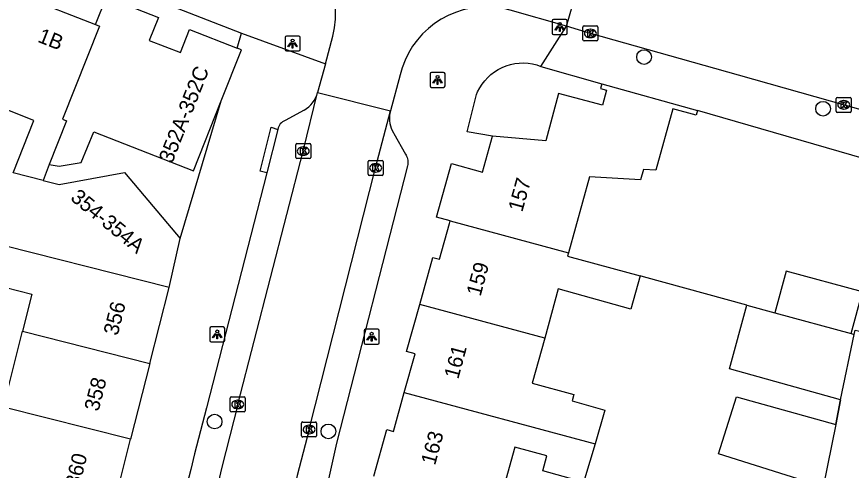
# Model space of a CAD drawing. Extents: x 161253 to 161848, y 384872 to 385383.
# Drawn here: x 161649.5 to 161705.2, y 385069.1 to 385099.3 of the extents above; entities that cross this region are included whole.
import ezdxf

# ---------------------------------------------------------------- set-up
doc = ezdxf.new("R2010")
doc.units = 0
for name, color, linetype in [('IMGEO_Boom', 7, 'Continuous'), ('IMGEO_Erf', 7, 'Continuous'), ('IMGEO_Hek', 7, 'Continuous'), ('IMGEO_Kolk', 7, 'Continuous'), ('IMGEO_Lichtpunt', 7, 'Continuous'), ('IMGEO_Pand', 7, 'Continuous'), ('IMGEO_Pand_nummerreeks', 7, 'Continuous'), ('IMGEO_Rijbaan_lokaal_open', 7, 'Continuous'), ('IMGEO_Voetpad_open', 7, 'Continuous')]:
    doc.layers.add(name, color=color, linetype=linetype)

msp = doc.modelspace()

# ---------------------------------------------------------------- linework, layer by layer
at = {"layer": 'IMGEO_Boom'}
for centre in [(161691.332, 385096.626), (161703.264, 385093.176), (161662.69, 385072.315), (161670.276, 385071.655)]:
    msp.add_circle(centre, 0.489, dxfattribs=at)
at = {"layer": 'IMGEO_Erf'}
msp.add_lwpolyline([(161698.188, 385080.085), (161691.283, 385081.97), (161691.078, 385082.026)], dxfattribs=at)
at = {"layer": 'IMGEO_Hek'}
msp.add_lwpolyline([(161704.441, 385073.771), (161704.117, 385072.125)], dxfattribs=at)
at = {"layer": 'IMGEO_Kolk'}
for p, q in [((161687.251, 385097.773), (161687.251, 385098.625)), ((161687.326, 385098.699), (161688.178, 385098.699)), ((161687.739, 385098.479), (161687.764, 385098.479)), ((161688.252, 385098.625), (161688.252, 385097.773)), ((161688.178, 385097.699), (161687.326, 385097.699)), ((161687.762, 385097.919), (161687.737, 385097.919)), ((161704.15, 385093.01), (161704.15, 385093.862)), ((161704.225, 385093.936), (161705.077, 385093.936)), ((161705.151, 385093.862), (161705.151, 385093.01)), ((161704.638, 385093.716), (161704.663, 385093.716)), ((161705.077, 385092.936), (161704.225, 385092.936)), ((161704.661, 385093.156), (161704.636, 385093.156)), ((161668.101, 385089.924), (161668.101, 385090.776)), ((161668.176, 385090.85), (161669.028, 385090.85)), ((161668.589, 385090.63), (161668.614, 385090.63)), ((161669.102, 385090.776), (161669.102, 385089.924)), ((161669.028, 385089.85), (161668.176, 385089.85)), ((161668.612, 385090.07), (161668.587, 385090.07)), ((161672.931, 385088.806), (161672.931, 385089.658)), ((161673.006, 385089.732), (161673.858, 385089.732)), ((161673.419, 385089.512), (161673.444, 385089.512)), ((161673.932, 385089.658), (161673.932, 385088.806)), ((161673.858, 385088.732), (161673.006, 385088.732)), ((161673.442, 385088.952), (161673.417, 385088.952)), ((161663.736, 385073.03), (161663.736, 385073.882)), ((161663.811, 385073.956), (161664.663, 385073.956)), ((161664.224, 385073.736), (161664.249, 385073.736)), ((161664.737, 385073.882), (161664.737, 385073.03)), ((161664.247, 385073.176), (161664.222, 385073.176)), ((161664.663, 385072.956), (161663.811, 385072.956)), ((161668.496, 385071.357), (161668.496, 385072.209)), ((161668.571, 385072.283), (161669.423, 385072.283)), ((161668.984, 385072.063), (161669.009, 385072.063)), ((161669.497, 385072.209), (161669.497, 385071.357)), ((161669.007, 385071.503), (161668.982, 385071.503)), ((161669.423, 385071.283), (161668.571, 385071.283))]:
    msp.add_line(p, q, dxfattribs=at)
for points in [[(161687.251, 385097.773), (161687.251, 385098.625)], [(161687.326, 385098.699), (161688.178, 385098.699)], [(161687.572, 385098.399), (161687.695, 385098.399), (161687.695, 385098.248), (161687.825, 385098.399), (161687.989, 385098.399), (161687.843, 385098.248), (161687.996, 385097.999), (161687.844, 385097.999), (161687.759, 385098.163), (161687.695, 385098.096), (161687.695, 385097.999), (161687.572, 385097.999), (161687.572, 385098.399)], [(161688.252, 385098.625), (161688.252, 385097.773)], [(161688.178, 385097.699), (161687.326, 385097.699)], [(161704.15, 385093.01), (161704.15, 385093.862)], [(161704.225, 385093.936), (161705.077, 385093.936)], [(161705.151, 385093.862), (161705.151, 385093.01)], [(161704.471, 385093.636), (161704.594, 385093.636), (161704.594, 385093.485), (161704.724, 385093.636), (161704.888, 385093.636), (161704.742, 385093.485), (161704.895, 385093.236), (161704.743, 385093.236), (161704.658, 385093.4), (161704.594, 385093.333), (161704.594, 385093.236), (161704.471, 385093.236), (161704.471, 385093.636)], [(161705.077, 385092.936), (161704.225, 385092.936)], [(161668.101, 385089.924), (161668.101, 385090.776)], [(161668.176, 385090.85), (161669.028, 385090.85)], [(161668.422, 385090.55), (161668.545, 385090.55), (161668.545, 385090.399), (161668.675, 385090.55), (161668.839, 385090.55), (161668.693, 385090.399), (161668.846, 385090.15), (161668.694, 385090.15), (161668.609, 385090.314), (161668.545, 385090.247), (161668.545, 385090.15), (161668.422, 385090.15), (161668.422, 385090.55)], [(161669.102, 385090.776), (161669.102, 385089.924)], [(161669.028, 385089.85), (161668.176, 385089.85)], [(161672.931, 385088.806), (161672.931, 385089.658)], [(161673.006, 385089.732), (161673.858, 385089.732)], [(161673.252, 385089.432), (161673.375, 385089.432), (161673.375, 385089.281), (161673.505, 385089.432), (161673.669, 385089.432), (161673.523, 385089.281), (161673.676, 385089.032), (161673.524, 385089.032), (161673.439, 385089.196), (161673.375, 385089.129), (161673.375, 385089.032), (161673.252, 385089.032), (161673.252, 385089.432)], [(161673.932, 385089.658), (161673.932, 385088.806)], [(161673.858, 385088.732), (161673.006, 385088.732)], [(161663.736, 385073.03), (161663.736, 385073.882)], [(161663.811, 385073.956), (161664.663, 385073.956)], [(161664.737, 385073.882), (161664.737, 385073.03)], [(161664.057, 385073.656), (161664.18, 385073.656), (161664.18, 385073.505), (161664.31, 385073.656), (161664.474, 385073.656), (161664.328, 385073.505), (161664.481, 385073.256), (161664.329, 385073.256), (161664.244, 385073.42), (161664.18, 385073.353), (161664.18, 385073.256), (161664.057, 385073.256), (161664.057, 385073.656)], [(161664.663, 385072.956), (161663.811, 385072.956)], [(161668.496, 385071.357), (161668.496, 385072.209)], [(161668.571, 385072.283), (161669.423, 385072.283)], [(161669.497, 385072.209), (161669.497, 385071.357)], [(161668.817, 385071.983), (161668.94, 385071.983), (161668.94, 385071.832), (161669.07, 385071.983), (161669.234, 385071.983), (161669.088, 385071.832), (161669.241, 385071.583), (161669.089, 385071.583), (161669.004, 385071.747), (161668.94, 385071.68), (161668.94, 385071.583), (161668.817, 385071.583), (161668.817, 385071.983)], [(161669.423, 385071.283), (161668.571, 385071.283)]]:
    msp.add_lwpolyline(points, dxfattribs=at)
for centre, start, end in [((161687.328, 385098.623), 91.552, 178.448), ((161687.328, 385098.623), 91.552, 178.448), ((161688.176, 385098.623), 1.552, 88.448), ((161688.176, 385098.623), 1.552, 88.448), ((161687.328, 385097.775), 181.552, 268.448), ((161687.328, 385097.775), 181.552, 268.448), ((161688.176, 385097.775), 271.552, 358.448), ((161688.176, 385097.775), 271.552, 358.448), ((161704.227, 385093.86), 91.552, 178.448), ((161704.227, 385093.86), 91.552, 178.448), ((161705.075, 385093.86), 1.552, 88.448), ((161705.075, 385093.86), 1.552, 88.448), ((161704.227, 385093.012), 181.552, 268.448), ((161704.227, 385093.012), 181.552, 268.448), ((161705.075, 385093.012), 271.552, 358.448), ((161705.075, 385093.012), 271.552, 358.448), ((161668.178, 385090.774), 91.552, 178.448), ((161668.178, 385090.774), 91.552, 178.448), ((161669.026, 385090.774), 1.552, 88.448), ((161669.026, 385090.774), 1.552, 88.448), ((161668.178, 385089.926), 181.552, 268.448), ((161668.178, 385089.926), 181.552, 268.448), ((161669.026, 385089.926), 271.552, 358.448), ((161669.026, 385089.926), 271.552, 358.448), ((161673.008, 385089.656), 91.552, 178.448), ((161673.008, 385089.656), 91.552, 178.448), ((161673.856, 385089.656), 1.552, 88.448), ((161673.856, 385089.656), 1.552, 88.448), ((161673.008, 385088.808), 181.552, 268.448), ((161673.008, 385088.808), 181.552, 268.448), ((161673.856, 385088.808), 271.552, 358.448), ((161673.856, 385088.808), 271.552, 358.448), ((161663.813, 385073.88), 91.552, 178.448), ((161663.813, 385073.88), 91.552, 178.448), ((161664.661, 385073.88), 1.552, 88.448), ((161664.661, 385073.88), 1.552, 88.448), ((161663.813, 385073.032), 181.552, 268.448), ((161663.813, 385073.032), 181.552, 268.448), ((161664.661, 385073.032), 271.552, 358.448), ((161664.661, 385073.032), 271.552, 358.448), ((161668.573, 385072.207), 91.552, 178.448), ((161668.573, 385072.207), 91.552, 178.448), ((161669.421, 385072.207), 1.552, 88.448), ((161669.421, 385072.207), 1.552, 88.448), ((161668.573, 385071.359), 181.552, 268.448), ((161668.573, 385071.359), 181.552, 268.448), ((161669.421, 385071.359), 271.552, 358.448), ((161669.421, 385071.359), 271.552, 358.448)]:
    msp.add_arc(centre, 0.0765, start, end, dxfattribs=at)
for centre, major_axis, ratio, start_param, end_param in [((161687.738, 385098.199), (-0.387, 0.002), 0.722429, 4.712389, 7.853982), ((161687.763, 385098.199), (-0.39, 0.002), 0.717154, 1.570796, 4.712389), ((161704.637, 385093.436), (-0.387, 0.002), 0.722429, 4.712389, 7.853982), ((161704.662, 385093.436), (-0.39, 0.002), 0.717154, 1.570796, 4.712389), ((161668.588, 385090.35), (-0.387, 0.002), 0.722429, 4.712389, 7.853982), ((161668.613, 385090.35), (-0.39, 0.002), 0.717154, 1.570796, 4.712389), ((161673.418, 385089.232), (-0.387, 0.002), 0.722429, 4.712389, 7.853982), ((161673.443, 385089.232), (-0.39, 0.002), 0.717154, 1.570796, 4.712389), ((161664.223, 385073.456), (-0.387, 0.002), 0.722429, 4.712389, 7.853982), ((161664.248, 385073.456), (-0.39, 0.002), 0.717154, 1.570796, 4.712389), ((161668.983, 385071.783), (-0.387, 0.002), 0.722429, 4.712389, 7.853982), ((161669.008, 385071.783), (-0.39, 0.002), 0.717154, 1.570796, 4.712389)]:
    msp.add_ellipse(centre, major_axis=major_axis, ratio=ratio, start_param=start_param, end_param=end_param, dxfattribs=at)
at = {"layer": 'IMGEO_Lichtpunt'}
for p, q in [((161685.206, 385099.031), (161685.206, 385098.224)), ((161685.206, 385099.031), (161685.206, 385098.224)), ((161686.108, 385099.126), (161685.3, 385099.126)), ((161686.108, 385099.126), (161685.3, 385099.126)), ((161686.202, 385098.224), (161686.202, 385099.031)), ((161686.202, 385098.224), (161686.202, 385099.031)), ((161667.396, 385097.93), (161667.396, 385097.123)), ((161667.396, 385097.93), (161667.396, 385097.123)), ((161668.298, 385098.025), (161667.49, 385098.025)), ((161668.298, 385098.025), (161667.49, 385098.025)), ((161668.392, 385097.123), (161668.392, 385097.93)), ((161668.392, 385097.123), (161668.392, 385097.93)), ((161685.3, 385098.13), (161686.108, 385098.13)), ((161685.3, 385098.13), (161686.108, 385098.13)), ((161667.49, 385097.029), (161668.298, 385097.029)), ((161667.49, 385097.029), (161668.298, 385097.029)), ((161677.061, 385095.502), (161677.061, 385094.695)), ((161677.061, 385095.502), (161677.061, 385094.695)), ((161677.963, 385095.597), (161677.155, 385095.597)), ((161677.963, 385095.597), (161677.155, 385095.597)), ((161678.057, 385094.695), (161678.057, 385095.502)), ((161678.057, 385094.695), (161678.057, 385095.502)), ((161677.155, 385094.601), (161677.963, 385094.601)), ((161677.155, 385094.601), (161677.963, 385094.601)), ((161662.368, 385078.528), (161662.368, 385077.721)), ((161662.368, 385078.528), (161662.368, 385077.721)), ((161663.27, 385078.623), (161662.462, 385078.623)), ((161663.27, 385078.623), (161662.462, 385078.623)), ((161663.364, 385077.721), (161663.364, 385078.528)), ((161663.364, 385077.721), (161663.364, 385078.528)), ((161672.666, 385078.371), (161672.666, 385077.564)), ((161672.666, 385078.371), (161672.666, 385077.564)), ((161673.568, 385078.466), (161672.76, 385078.466)), ((161673.568, 385078.466), (161672.76, 385078.466)), ((161673.662, 385077.564), (161673.662, 385078.371)), ((161673.662, 385077.564), (161673.662, 385078.371)), ((161662.462, 385077.627), (161663.27, 385077.627)), ((161662.462, 385077.627), (161663.27, 385077.627)), ((161672.76, 385077.47), (161673.568, 385077.47)), ((161672.76, 385077.47), (161673.568, 385077.47))]:
    msp.add_line(p, q, dxfattribs=at)
for points in [[(161685.58, 385098.695), (161685.619, 385098.667), (161685.431, 385098.405), (161685.393, 385098.432), (161685.58, 385098.695)], [(161685.682, 385098.647), (161685.729, 385098.647), (161685.729, 385098.325), (161685.682, 385098.325), (161685.682, 385098.647)], [(161685.792, 385098.667), (161685.83, 385098.694), (161686.017, 385098.432), (161685.978, 385098.404), (161685.792, 385098.667)], [(161667.77, 385097.594), (161667.809, 385097.566), (161667.621, 385097.304), (161667.583, 385097.331), (161667.77, 385097.594)], [(161667.872, 385097.546), (161667.919, 385097.546), (161667.919, 385097.224), (161667.872, 385097.224), (161667.872, 385097.546)], [(161667.982, 385097.566), (161668.02, 385097.593), (161668.207, 385097.331), (161668.168, 385097.303), (161667.982, 385097.566)], [(161677.435, 385095.166), (161677.474, 385095.138), (161677.286, 385094.876), (161677.248, 385094.903), (161677.435, 385095.166)], [(161677.537, 385095.118), (161677.584, 385095.118), (161677.584, 385094.796), (161677.537, 385094.796), (161677.537, 385095.118)], [(161677.647, 385095.138), (161677.685, 385095.165), (161677.872, 385094.903), (161677.833, 385094.875), (161677.647, 385095.138)], [(161662.742, 385078.192), (161662.781, 385078.164), (161662.593, 385077.902), (161662.555, 385077.929), (161662.742, 385078.192)], [(161662.844, 385078.144), (161662.891, 385078.144), (161662.891, 385077.822), (161662.844, 385077.822), (161662.844, 385078.144)], [(161662.954, 385078.164), (161662.992, 385078.191), (161663.179, 385077.929), (161663.14, 385077.901), (161662.954, 385078.164)], [(161673.04, 385078.035), (161673.079, 385078.007), (161672.891, 385077.745), (161672.853, 385077.772), (161673.04, 385078.035)], [(161673.142, 385077.987), (161673.189, 385077.987), (161673.189, 385077.665), (161673.142, 385077.665), (161673.142, 385077.987)], [(161673.252, 385078.007), (161673.29, 385078.034), (161673.477, 385077.772), (161673.438, 385077.744), (161673.252, 385078.007)]]:
    msp.add_lwpolyline(points, dxfattribs=at)
for centre in [(161685.705, 385098.829), (161667.895, 385097.728), (161677.56, 385095.3), (161662.867, 385078.326), (161673.165, 385078.169)]:
    msp.add_circle(centre, 0.0994, dxfattribs=at)
for centre, start, end in [((161685.3, 385099.031), 90, 180), ((161685.3, 385099.031), 90, 180), ((161686.108, 385099.031), 0, 90), ((161686.108, 385099.031), 0, 90), ((161685.3, 385098.224), 180, 270), ((161685.3, 385098.224), 180, 270), ((161686.108, 385098.224), 270, 0), ((161686.108, 385098.224), 270, 360), ((161667.49, 385097.93), 90, 180), ((161667.49, 385097.93), 90, 180), ((161668.298, 385097.93), 0, 90), ((161668.298, 385097.93), 0, 90), ((161667.49, 385097.123), 180, 270), ((161667.49, 385097.123), 180, 270), ((161668.298, 385097.123), 270, 0), ((161668.298, 385097.123), 270, 360), ((161677.155, 385095.502), 90, 180), ((161677.155, 385095.502), 90, 180), ((161677.963, 385095.502), 0, 90), ((161677.963, 385095.502), 0, 90), ((161677.155, 385094.695), 180, 270), ((161677.155, 385094.695), 180, 270), ((161677.963, 385094.695), 270, 0), ((161677.963, 385094.695), 270, 360), ((161662.462, 385078.528), 90, 180), ((161662.462, 385078.528), 90, 180), ((161663.27, 385078.528), 0, 90), ((161663.27, 385078.528), 0, 90), ((161672.76, 385078.371), 90, 180), ((161672.76, 385078.371), 90, 180), ((161673.568, 385078.371), 0, 90), ((161673.568, 385078.371), 0, 90), ((161662.462, 385077.721), 180, 270), ((161662.462, 385077.721), 180, 270), ((161663.27, 385077.721), 270, 0), ((161663.27, 385077.721), 270, 360), ((161672.76, 385077.564), 180, 270), ((161672.76, 385077.564), 180, 270), ((161673.568, 385077.564), 270, 0), ((161673.568, 385077.564), 270, 360)]:
    msp.add_arc(centre, 0.0946, start, end, dxfattribs=at)
at = {"layer": 'IMGEO_Pand'}
for points in [[(161649.844, 385100.733), (161654.75, 385098.796)], [(161654.75, 385098.796), (161655.475, 385100.632), (161658.947, 385099.269), (161658.338, 385097.734), (161660.407, 385096.922), (161661.01, 385098.46), (161664.187, 385097.213)], [(161654.75, 385098.796), (161655.013, 385098.692), (161652.558, 385092.47), (161652.823, 385092.366), (161651.664, 385089.462)], [(161663.138, 385093.695), (161664.483, 385097.097), (161664.187, 385097.213)], [(161688.519, 385094.827), (161688.433, 385094.519), (161688.837, 385094.406), (161688.558, 385093.404), (161685.625, 385094.2), (161684.77, 385091.03), (161681.223, 385091.339)], [(161688.519, 385094.827), (161694.886, 385093.053)], [(161649.268, 385088.892), (161650.646, 385092.395), (161647.102, 385093.79)], [(161651.664, 385089.462), (161652.337, 385089.349), (161653.799, 385089.581), (161654.645, 385091.647), (161661.293, 385089.025), (161663.138, 385093.695)], [(161694.886, 385093.053), (161694.8, 385092.745), (161693.259, 385093.174), (161692.116, 385089.073), (161691.294, 385089.125), (161691.1, 385088.429), (161687.699, 385088.644), (161686.286, 385083.569)], [(161678.395, 385085.693), (161677.492, 385085.936), (161678.492, 385089.527), (161680.558, 385088.951), (161681.223, 385091.339)], [(161651.664, 385089.462), (161651.254, 385088.388)], [(161651.254, 385088.388), (161649.268, 385088.892)], [(161651.254, 385088.388), (161652.337, 385088.113), (161656.674, 385088.935), (161660.157, 385084.816), (161660.406, 385084.529)], [(161676.371, 385080.127), (161677.244, 385083.26), (161677.683, 385083.137), (161678.35, 385085.532), (161678.395, 385085.693)], [(161678.395, 385085.693), (161686.286, 385083.569)], [(161646.818, 385084.494), (161646.154, 385081.921), (161650.498, 385080.82), (161649.879, 385078.335)], [(161659.654, 385081.261), (161646.818, 385084.494)], [(161659.654, 385081.261), (161660.406, 385084.529)], [(161686.286, 385083.569), (161686.225, 385083.351), (161691.078, 385082.026)], [(161705.134, 385078.188), (161705.891, 385080.961), (161700.815, 385082.347), (161700.058, 385079.574)], [(161691.078, 385082.026), (161690.459, 385079.804), (161685.613, 385081.154), (161684.703, 385077.885)], [(161658.369, 385076.191), (161659.654, 385081.261)], [(161675.339, 385074.248), (161676.061, 385076.838), (161675.499, 385076.995), (161676.371, 385080.127)], [(161684.703, 385077.885), (161676.371, 385080.127)], [(161704.441, 385073.771), (161697.038, 385075.832), (161698.188, 385080.085)], [(161698.188, 385080.085), (161700.058, 385079.574)], [(161700.058, 385079.574), (161705.134, 385078.188)], [(161648.616, 385073.271), (161649.879, 385078.335)], [(161649.879, 385078.335), (161658.369, 385076.191)], [(161705.134, 385078.188), (161705.35, 385078.129)], [(161684.703, 385077.885), (161683.867, 385074.884), (161686.648, 385074.109), (161686.53, 385073.686), (161688.704, 385073.081), (161688.074, 385070.82)], [(161704.441, 385073.771), (161705.35, 385078.129)], [(161658.369, 385076.191), (161657.09, 385071.131)], [(161673.309, 385068.67), (161674.175, 385071.779), (161674.617, 385071.656), (161675.339, 385074.248)], [(161675.339, 385074.248), (161688.074, 385070.82)], [(161703.28, 385067.948), (161696.289, 385070.15), (161697.492, 385073.969), (161704.117, 385072.125)], [(161657.09, 385071.131), (161648.616, 385073.271)], [(161704.117, 385072.125), (161703.28, 385067.948)], [(161655.811, 385066.071), (161657.09, 385071.131)], [(161688.074, 385070.82), (161687.355, 385068.461), (161687.301, 385068.267), (161684.57, 385069.027), (161684.846, 385070.018), (161682.712, 385070.612), (161681.553, 385066.451)]]:
    msp.add_lwpolyline(points, dxfattribs=at)
at = {"layer": 'IMGEO_Rijbaan_lokaal_open'}
for points in [[(161670.083, 385096.175), (161670.582, 385098.007), (161670.689, 385098.575), (161670.745, 385099.15), (161670.749, 385099.728), (161670.701, 385100.304), (161670.603, 385100.874), (161670.454, 385101.432), (161670.255, 385101.975), (161670.009, 385102.498), (161669.717, 385102.997), (161669.382, 385103.468), (161669.006, 385103.907), (161668.592, 385104.311), (161668.144, 385104.676), (161667.665, 385104.999), (161667.159, 385105.279), (161666.63, 385105.512), (161666.091, 385105.695), (161664.299, 385106.388)], [(161686.148, 385098.677), (161688.097, 385105.371)], [(161686.148, 385098.677), (161682.408, 385099.761), (161681.892, 385099.879), (161681.367, 385099.951), (161680.838, 385099.976), (161680.308, 385099.953), (161679.783, 385099.883), (161679.266, 385099.766), (161678.761, 385099.604), (161678.274, 385099.397), (161677.806, 385099.148), (161677.363, 385098.858), (161676.947, 385098.529), (161676.562, 385098.164), (161676.212, 385097.767), (161675.898, 385097.34), (161675.624, 385096.886), (161675.392, 385096.41), (161675.202, 385095.915), (161675.068, 385095.448), (161674.419, 385093.044)], [(161709.086, 385080.709), (161710.176, 385085.852), (161710.267, 385086.4), (161710.308, 385086.953), (161710.299, 385087.508), (161710.242, 385088.06), (161710.135, 385088.604), (161709.98, 385089.137), (161709.777, 385089.654), (161709.53, 385090.151), (161709.239, 385090.623), (161708.907, 385091.068), (161708.537, 385091.482), (161708.131, 385091.86), (161707.693, 385092.201), (161707.226, 385092.501), (161706.735, 385092.759), (161706.222, 385092.971), (161705.809, 385093.105), (161697.639, 385095.416), (161687.752, 385098.199), (161686.148, 385098.677)], [(161670.083, 385096.175), (161669.559, 385094.249)], [(161664.237, 385073.456), (161668.602, 385090.35), (161669.559, 385094.249)], [(161669.559, 385094.249), (161674.419, 385093.044)], [(161668.997, 385071.783), (161673.432, 385089.232), (161674.419, 385093.044)]]:
    msp.add_lwpolyline(points, dxfattribs=at)
for centre, radius, start, end in [((162178.2, 384941.762), 530.567, 165.6282, 169.35845), ((162111.197, 384956.152), 457.068, 165.34579, 169.59072)]:
    msp.add_arc(centre, radius, start, end, dxfattribs=at)
at = {"layer": 'IMGEO_Voetpad_open'}
for points in [[(161646.03, 385105.403), (161664.489, 385098.225)], [(161664.187, 385097.213), (161664.489, 385098.225)], [(161664.489, 385098.225), (161670.083, 385096.175)], [(161684.448, 385096.001), (161686.148, 385098.677)], [(161681.223, 385091.339), (161679.542, 385091.647), (161680.159, 385094.122), (161680.234, 385094.301), (161680.368, 385094.564), (161680.525, 385094.813), (161680.704, 385095.048), (161680.902, 385095.266), (161681.12, 385095.465), (161681.354, 385095.643), (161681.604, 385095.801), (161681.866, 385095.935), (161682.14, 385096.045), (161682.422, 385096.13), (161682.71, 385096.19), (161683.003, 385096.224), (161683.298, 385096.232), (161683.592, 385096.213), (161683.884, 385096.168), (161684.17, 385096.097), (161684.448, 385096.001)], [(161684.448, 385096.001), (161688.519, 385094.827)], [(161660.406, 385084.529), (161663.138, 385093.695)], [(161674.419, 385093.044), (161674.381, 385092.878), (161674.358, 385092.71), (161674.35, 385092.54), (161674.358, 385092.37), (161674.381, 385092.201), (161674.419, 385092.035), (161674.471, 385091.873), (161674.538, 385091.717), (161674.618, 385091.567), (161674.649, 385091.517), (161675.429, 385090.139), (161675.458, 385090.087), (161675.497, 385090.005), (161675.529, 385089.919), (161675.553, 385089.831), (161675.569, 385089.741), (161675.576, 385089.65), (161675.576, 385089.559), (161675.567, 385089.468), (161675.551, 385089.379), (161670.83, 385070.871), (161663.603, 385038.359)], [(161668.668, 385093.088), (161667.4, 385092.4)], [(161705.35, 385078.129), (161705.415, 385078.403), (161706.001, 385078.274), (161706.582, 385080.923), (161705.996, 385081.052), (161707.725, 385089.351), (161694.886, 385093.053)], [(161666.171, 385088.892), (161665.73, 385089.018), (161666.471, 385091.946), (161666.9, 385091.801)], [(161666.9, 385091.801), (161666.171, 385088.892)], [(161666.171, 385088.892), (161662.148, 385073.222)], [(161704.117, 385072.125), (161704.441, 385073.771)]]:
    msp.add_lwpolyline(points, dxfattribs=at)
for centre, radius, start, end in [((161667.712, 385094.744), 1.913, 300.0027, 344.989), ((161667.693, 385091.647), 0.808, 111.2711, 169.0238), ((162106.071, 384957.101), 458.859, 165.34111, 169.56638)]:
    msp.add_arc(centre, radius, start, end, dxfattribs=at)

# ---------------------------------------------------------------- texts
at = {"layer": 'IMGEO_Pand_nummerreeks'}
for s, rotation, p in [('1B', 338.4568, (161650.832, 385097.655)), ('352A-352C', 68.4398, (161659.858, 385089.474)), ('157', 74.4387, (161683.207, 385086.239)), ('354-354A', 320.718, (161653.018, 385087.137)), ('159', 74.9372, (161680.426, 385080.62)), ('356', 75.817, (161656.228, 385078.001)), ('161', 74.9372, (161678.939, 385075.097)), ('358', 75.817, (161654.948, 385072.943)), ('163', 74.9372, (161677.394, 385069.354)), ('360', 75.8195, (161653.669, 385067.882))]:
    msp.add_text(s, height=1, rotation=rotation, dxfattribs=at).set_placement(p)

doc.saveas('drawing.dxf')
